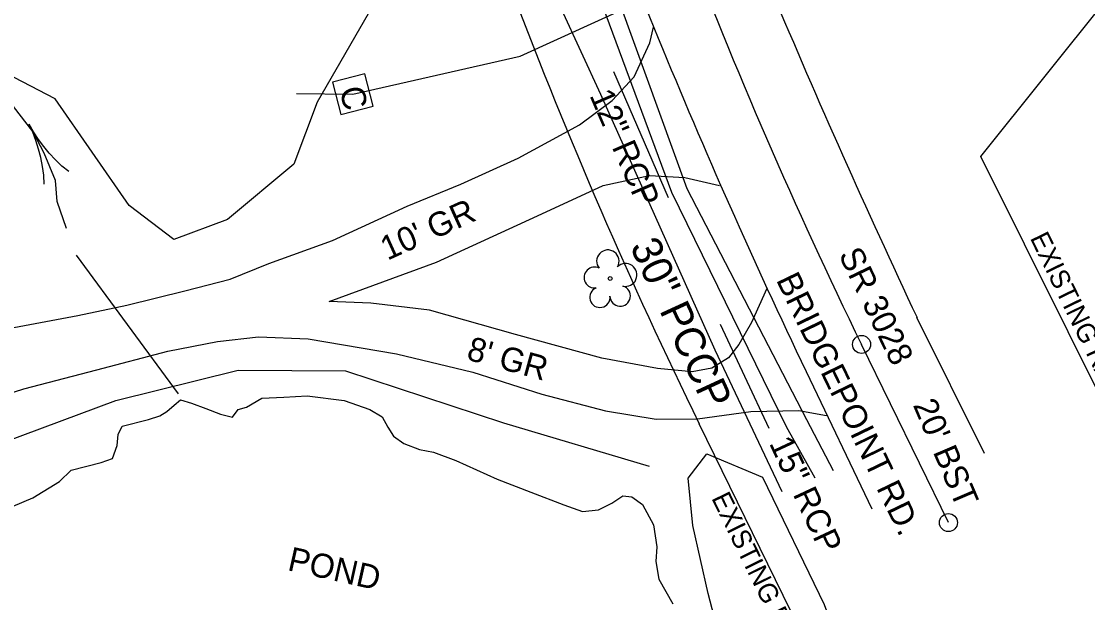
# Model space of a CAD drawing. Extents: x 1784037 to 1786391, y 840555 to 842045.
# Drawn here: x 1785567.5 to 1785744.6, y 841214.2 to 841310.7 of the extents above; entities that cross this region are included whole.
import ezdxf

# ---------------------------------------------------------------- set-up
doc = ezdxf.new("R2010")
doc.units = 0
for name, color, linetype in [('Exist Horizontal Alignment', 7, 'Continuous'), ('Exist Horizontal Alignment Station Label', 7, 'Continuous'), ('Exist Hydro Stream Flow Arrow CELL', 7, 'Continuous'), ('Exist Hydro Stream or Body of Water', 7, 'Continuous'), ('Exist Hydro Stream or Body of Water Text', 7, 'Continuous'), ('Exist Other Culture Dam', 7, 'Continuous'), ('Exist Right of Way Line', 7, 'Continuous'), ('Exist Right of Way Line Text', 7, 'Continuous'), ('Exist Roads EOP', 7, 'Continuous'), ('Exist Roads EOP Text', 7, 'Continuous'), ('Exist Roads Soil', 7, 'Continuous'), ('Exist Roads Soil Text', 7, 'Continuous'), ('Exist Structure Minor Culvert Topo', 7, 'Continuous'), ('Exist Structure Minor Pipes RCP 12 Inch', 7, 'Continuous'), ('Exist Structure Minor Pipes RCP 12 Inch Text', 7, 'Continuous'), ('Exist Structure Minor Pipes RCP 15 Inch', 7, 'Continuous'), ('Exist Structure Minor Pipes RCP 15 Inch Text', 7, 'Continuous'), ('Exist Utilities Telephone UG Cable SUE LOS B', 7, 'Continuous'), ('Exist Utilities TV Pedestal CELL', 7, 'Continuous'), ('Exist Utilities TV UG Cable SUE LOS B', 7, 'Continuous'), ('Exist Utilities Water UG Line SUE LOS B', 7, 'Continuous'), ('Exist Utilities Water UG Line SUE LOS B Text', 7, 'Continuous'), ('Exist Vegetation Tree CELL', 7, 'Continuous'), ('Exist Vegetation Woods Line', 7, 'Continuous')]:
    doc.layers.add(name, color=color, linetype=linetype)

msp = doc.modelspace()

# ---------------------------------------------------------------- linework, layer by layer
at = {"layer": 'Exist Horizontal Alignment'}
msp.add_line((1785721.46, 841227.49), (1785707.02, 841257.05), dxfattribs=at)
msp.add_arc((1786448.22, 841619.32), 825, 200.80994, 206.04741, dxfattribs=at)
at = {"layer": 'Exist Horizontal Alignment Station Label'}
for centre in [(1785707.02, 841257.05), (1785707.02, 841257.05), (1785721.46, 841227.49), (1785721.46, 841227.49)]:
    msp.add_circle(centre, 1.5, dxfattribs=at)
at = {"layer": 'Exist Hydro Stream Flow Arrow CELL'}
msp.add_line((1785571.04, 841289.17), (1785571.04, 841289.17), dxfattribs=at)
for points in [[(1785575.34, 841285.74), (1785574.2, 841286.66), (1785573.14, 841287.72), (1785572.12, 841288.79), (1785571.2, 841289.91), (1785570.33, 841291.1), (1785569.51, 841292.36), (1785568.79, 841293.63)], [(1785571.26, 841283.67), (1785571.19, 841285.14), (1785570.96, 841286.62), (1785570.71, 841288.08), (1785570.35, 841289.48), (1785569.9, 841290.89), (1785569.38, 841292.29), (1785568.79, 841293.63)]]:
    msp.add_lwpolyline(points, dxfattribs=at)
at = {"layer": 'Exist Hydro Stream or Body of Water'}
for points in [[(1785575, 841276.31), (1785573.42, 841280.77), (1785573.16, 841284.27), (1785571.24, 841288.83), (1785569.37, 841292.43), (1785566.19, 841296.54)], [(1785590.49, 841245.19), (1785591.64, 841245.91), (1785592.84, 841246.98), (1785593.93, 841247.85), (1785595.72, 841247.31), (1785598.14, 841246.4), (1785600.55, 841245.48), (1785602.56, 841244.96), (1785603.49, 841246.25), (1785604.87, 841246.65), (1785607.44, 841248.12), (1785611.09, 841248.31), (1785614.93, 841248.55), (1785621.07, 841247.77), (1785625.37, 841246.26), (1785627.39, 841245.02), (1785628.32, 841243.33), (1785629.27, 841241.82), (1785630.98, 841240.63), (1785633.62, 841239.63), (1785635.94, 841239.15), (1785639.62, 841237.76), (1785646.5, 841234.68), (1785652.07, 841232.54), (1785657.59, 841230.44), (1785660.69, 841229.33), (1785663.31, 841229.62), (1785665.52, 841230.69), (1785667.37, 841231.93), (1785668.89, 841231.76), (1785670.63, 841230.49), (1785672.46, 841227.1), (1785673.01, 841223.43), (1785672.85, 841221.02), (1785673.33, 841218.11), (1785675.67, 841214.02)], [(1785560.14, 841227.91), (1785562.39, 841228.67), (1785569.38, 841231.57), (1785573.81, 841234.31), (1785575.77, 841236.16), (1785580.74, 841237.46), (1785582.6, 841238.12), (1785583.41, 841240.26), (1785583.53, 841242.13), (1785584.24, 841243.49), (1785588.57, 841244.61), (1785590.49, 841245.19)]]:
    msp.add_lwpolyline(points, dxfattribs=at)
at = {"layer": 'Exist Other Culture Dam'}
msp.add_lwpolyline([(1785546.13, 841233.95), (1785583.14, 841247.75), (1785603.5, 841252.78), (1785621.29, 841252.7), (1785647.55, 841244.05), (1785671.74, 841236.82)], dxfattribs=at)
at = {"layer": 'Exist Right of Way Line'}
for p, q in [((1785726.82, 841288.27), (1785790.29, 841367.49)), ((1785754.5, 841232.67), (1785726.82, 841288.27)), ((1785699.04, 841205.06), (1785680.07, 841243.87))]:
    msp.add_line(p, q, dxfattribs=at)
msp.add_arc((1786448.22, 841619.32), 855, 200.80994, 206.04741, dxfattribs=at)
at = {"layer": 'Exist Roads EOP'}
for p, q in [((1785727.46, 841238.96), (1785716.23, 841261.51)), ((1785697.8, 841252.58), (1785708.75, 841229.77))]:
    msp.add_line(p, q, dxfattribs=at)
for centre, major_axis, ratio, start_param, end_param in [((1785989.36, 841442.94), (49.85, -344.94), 0.9853, 4.793768, 4.968884), ((1786622.45, 841735.84), (393.07, -1138.75), 0.846372, 4.790091, 4.839473), ((1786411.61, 841628.45), (284.5, -870.37), 0.878155, 4.794677, 4.860907)]:
    msp.add_ellipse(centre, major_axis=major_axis, ratio=ratio, start_param=start_param, end_param=end_param, dxfattribs=at)
at = {"layer": 'Exist Roads Soil'}
for points in [[(1785521.78, 841243.74), (1785523.6, 841244.5), (1785532.36, 841248.53), (1785542.85, 841252.68), (1785554.14, 841256.83), (1785565.36, 841259.72), (1785576.87, 841261.85), (1785584.98, 841263.6), (1785594.61, 841265.95), (1785602.17, 841267.9), (1785608.58, 841270.51), (1785619.17, 841274.32), (1785631.57, 841280.01), (1785640.45, 841283.67), (1785650.01, 841287.99), (1785660.2, 841293.53), (1785665.62, 841297.56), (1785669.23, 841301.5), (1785671.85, 841307.12), (1785672.45, 841309.73)], [(1785691.27, 841266.34), (1785688.75, 841260.7), (1785686.66, 841257.07), (1785684.91, 841254.82), (1785682.16, 841253.12), (1785678.9, 841252.53), (1785673.12, 841253.07), (1785663.89, 841254.78), (1785649.55, 841258.72), (1785635.28, 841262.73), (1785625.52, 841263.88), (1785618.61, 841264.19), (1785636.44, 841270.69), (1785653.18, 841278.43), (1785664.12, 841283.45), (1785671.82, 841285.1), (1785677.65, 841284.79), (1785683.41, 841283.44)], [(1785528.23, 841234.37), (1785533.31, 841237.07), (1785543.95, 841241.69), (1785554.36, 841245.38), (1785567.86, 841249.67), (1785580.02, 841252.85), (1785591.8, 841255.96), (1785600.06, 841257.55), (1785606.87, 841258.34), (1785615.12, 841257.98), (1785629.8, 841255.52), (1785642.44, 841252.45), (1785653.94, 841248.79), (1785664.51, 841246.05), (1785672.92, 841244.67), (1785679.79, 841244.71), (1785688.61, 841245.93), (1785696.59, 841246.1), (1785701.2, 841245.27)]]:
    msp.add_lwpolyline(points, dxfattribs=at)
at = {"layer": 'Exist Structure Minor Culvert Topo'}
msp.add_line((1785593.58, 841248.88), (1785576.64, 841271.85), dxfattribs=at)
at = {"layer": 'Exist Structure Minor Pipes RCP 12 Inch'}
msp.add_line((1785665.85, 841302.37), (1785674.92, 841281.43), dxfattribs=at)
at = {"layer": 'Exist Structure Minor Pipes RCP 15 Inch'}
msp.add_line((1785683.56, 841260.44), (1785691.63, 841243.18), dxfattribs=at)
at = {"layer": 'Exist Utilities Telephone UG Cable SUE LOS B'}
for points in [[(1785644.61, 841325.43), (1785647.9, 841325.52), (1785657.52, 841327.98), (1785661.47, 841327.56), (1785664.59, 841319.9), (1785677.99, 841282.96), (1785697.86, 841244.57), (1785702.29, 841236.13)], [(1785644.61, 841325.43), (1785645.52, 841324.94), (1785656.19, 841325.97), (1785659.04, 841325.87), (1785661.78, 841319.28), (1785675.44, 841282.34), (1785694.51, 841243.43), (1785699.29, 841234.9)]]:
    msp.add_lwpolyline(points, dxfattribs=at)
at = {"layer": 'Exist Utilities TV Pedestal CELL'}
msp.add_line((1785622.54, 841298.59), (1785622.54, 841298.59), dxfattribs=at)
msp.add_lwpolyline([(1785619.16, 841300.6), (1785620.53, 841295.22), (1785625.91, 841296.59), (1785624.54, 841301.97), (1785619.16, 841300.6)], dxfattribs=at)
at = {"layer": 'Exist Utilities TV UG Cable SUE LOS B'}
msp.add_line((1785613.2, 841298.73), (1785622.54, 841298.59), dxfattribs=at)
msp.add_lwpolyline([(1785622.54, 841298.59), (1785650.32, 841304.92), (1785683.17, 841319.9), (1785709.79, 841338.02)], dxfattribs=at)
at = {"layer": 'Exist Utilities Water UG Line SUE LOS B'}
msp.add_lwpolyline([(1785643.26, 841344.47), (1785646.15, 841335.94), (1785650.58, 841326.98), (1785663.66, 841298.6), (1785682.66, 841256.17), (1785693.76, 841232.62)], dxfattribs=at)
at = {"layer": 'Exist Vegetation Tree CELL'}
msp.add_line((1785665.27, 841268), (1785665.27, 841268), dxfattribs=at)
msp.add_circle((1785665.27, 841268), 0.326, dxfattribs=at)
for centre, radius, start, end in [((1785664.88, 841270.88), 1.86, 330.1651, 219.7134), ((1785662.66, 841268.16), 1.73, 62.6636, 279.3457), ((1785667.82, 841268.59), 1.9, 257.1011, 134.1999), ((1785663.56, 841264.88), 1.69, 111.5671, 6.231), ((1785666.94, 841265.1), 1.7, 181.2822, 74.56)]:
    msp.add_arc(centre, radius, start, end, dxfattribs=at)
at = {"layer": 'Exist Vegetation Woods Line'}
for points in [[(1785557.37, 841428.59), (1785570.39, 841427.86), (1785582.44, 841423.57), (1785594.29, 841417.1), (1785603.83, 841403.39), (1785611, 841389.09), (1785623.68, 841374.66), (1785634.97, 841362.92), (1785639.47, 841354.38), (1785646.71, 841344.25), (1785647.83, 841335.14), (1785641.06, 841324.9), (1785626.76, 841314.89), (1785616.63, 841297.25), (1785612.72, 841286.96), (1785601.71, 841277.8), (1785592.82, 841274.48), (1785585.4, 841280.1), (1785573.09, 841297.82), (1785560.8, 841304.2)], [(1785685.97, 841198.54), (1785685.9, 841198.94), (1785681.57, 841215.71), (1785679.02, 841227.02), (1785678.24, 841234.86), (1785681.34, 841238.9), (1785690.57, 841235.03), (1785700.83, 841213.86), (1785705.42, 841201.46)]]:
    msp.add_lwpolyline(points, dxfattribs=at)

# ---------------------------------------------------------------- texts
at = {"layer": 'Exist Hydro Stream or Body of Water Text'}
msp.add_text('POND', height=4, rotation=347.3599, dxfattribs=at).set_placement((1785611.53, 841219.6))
at = {"layer": 'Exist Right of Way Line Text'}
for rotation, p in [(295.9515, (1785734.95, 841274.73)), (296.0474, (1785682.04, 841231.55))]:
    msp.add_text('EXISTING R/W', height=3.2, rotation=rotation, dxfattribs=at).set_placement(p)
at = {"layer": 'Exist Roads EOP Text'}
for s, rotation, p in [('SR 3028', 295.7541, (1785703.15, 841271.97)), ('BRIDGEPOINT RD.', 295.7541, (1785692.77, 841267.78)), ("20' BST", 293.0631, (1785715.51, 841247.02))]:
    msp.add_text(s, height=4, rotation=rotation, dxfattribs=at).set_placement(p)
at = {"layer": 'Exist Roads Soil Text'}
for s, rotation, p in [("10' GR", 24.3622, (1785628.27, 841270.94)), ("8' GR", 344.6384, (1785641.24, 841254.59))]:
    msp.add_text(s, height=4, rotation=rotation, dxfattribs=at).set_placement(p)
at = {"layer": 'Exist Structure Minor Pipes RCP 12 Inch Text'}
msp.add_text('12" RCP', height=4, rotation=293.4085, dxfattribs=at).set_placement((1785661.79, 841298.41))
at = {"layer": 'Exist Structure Minor Pipes RCP 15 Inch Text'}
msp.add_text('15" RCP', height=4, rotation=295.0528, dxfattribs=at).set_placement((1785691.61, 841240.67))
at = {"layer": 'Exist Utilities TV Pedestal CELL'}
msp.add_text('C', height=4, rotation=284.2957, dxfattribs=at).set_placement((1785620.28, 841299.36))
at = {"layer": 'Exist Utilities Water UG Line SUE LOS B Text'}
msp.add_text('30" PCCP', height=5, rotation=294.7444, dxfattribs=at).set_placement((1785668.5, 841273.33))

doc.saveas('drawing.dxf')
